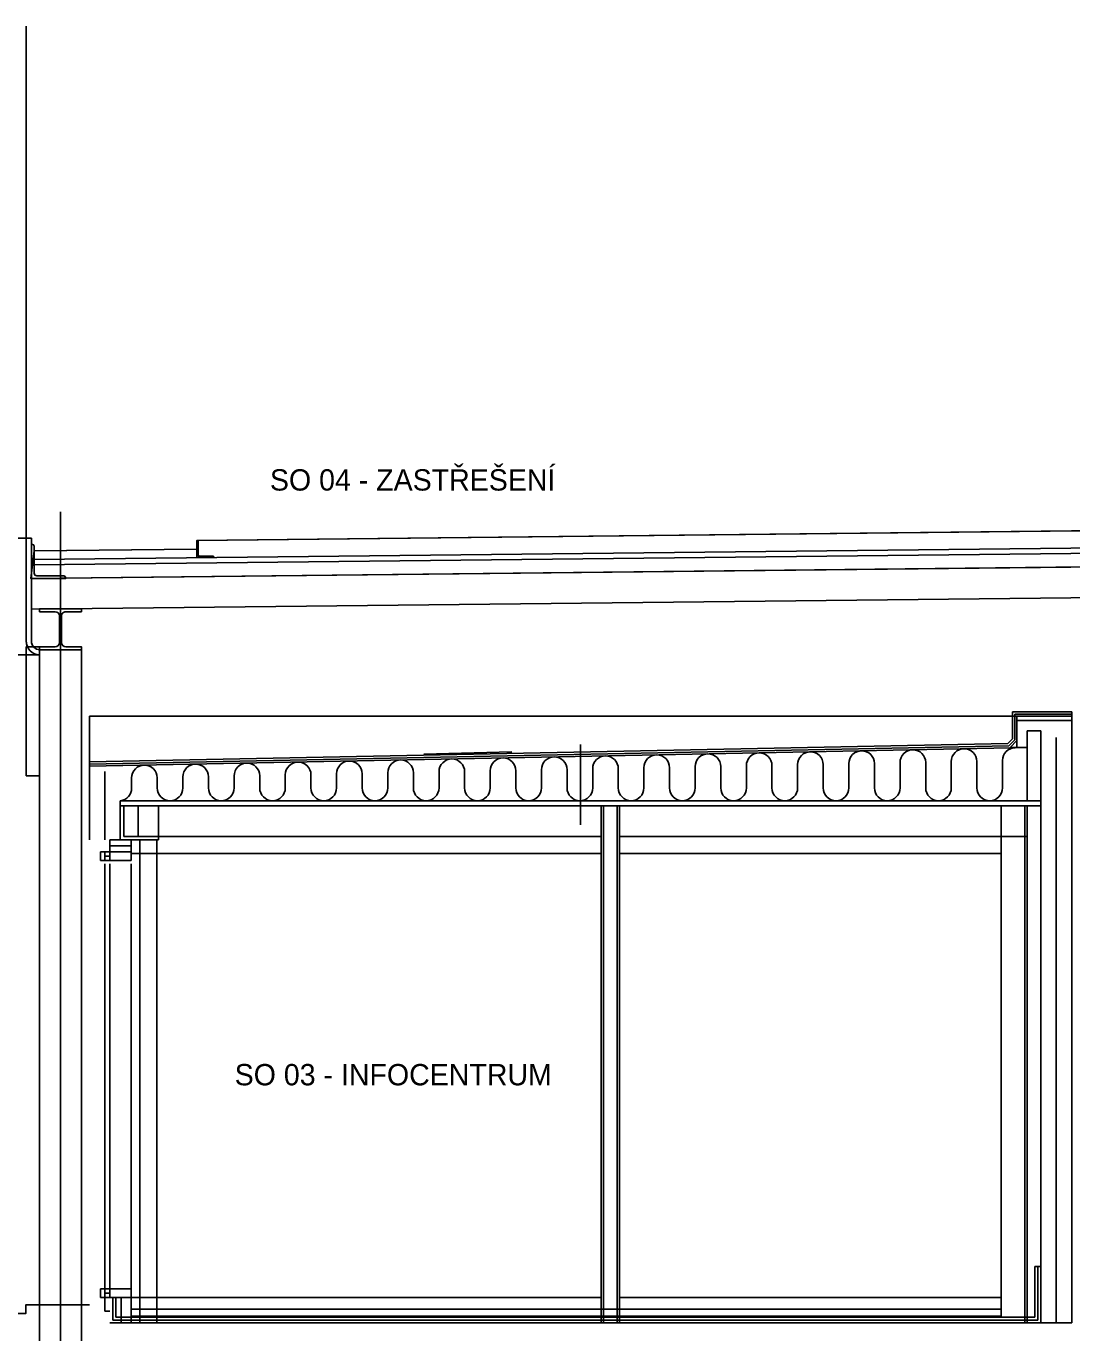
# Model space of a CAD drawing. Extents: x -438410 to -437811, y -1133174 to -1132817.
# Drawn here: x -437993.1 to -437962.48, y -1133028.74 to -1132990.45 of the extents above; entities that cross this region are included whole.
import ezdxf

# ---------------------------------------------------------------- set-up
doc = ezdxf.new("R2010")
doc.units = 0
for name, color, linetype in [('0100-STENY_REZ', 7, 'Continuous'), ('Default', 7, 'Continuous'), ('OSY', 7, 'Continuous'), ('S_IZOLACE', 7, 'Continuous'), ('S_KOTY_DILCI', 7, 'Continuous'), ('S_RASTR', 7, 'Continuous'), ('S_SKLO', 7, 'Continuous'), ('S_STENY_PODROVINOU', 7, 'Continuous'), ('S_STENY_REZ', 7, 'Continuous'), ('SILNA 1', 7, 'Continuous'), ('SILNA 2', 7, 'Continuous'), ('TECKA', 7, 'Continuous'), ('TENKA', 7, 'Continuous')]:
    doc.layers.add(name, color=color, linetype=linetype)

# ---------------------------------------------------------------- blocks, each defined once
blk = doc.blocks.new('fasada_sloupek_125')
at = {"layer": 'Default'}
for p, q in [((-0.25, 1.55), (-0.25, 1.25)), ((0, 1.55), (0, 1.25)), ((0.25, 1.55), (0.25, 1.25))]:
    blk.add_line(p, q, dxfattribs=at)
for points in [[(0.25, 1.55), (-0.25, 1.55), (-0.25, 1.8), (0.25, 1.8)], [(0.25, 0), (-0.25, 0), (-0.25, 1.25), (0.25, 1.25)]]:
    blk.add_lwpolyline(points, close=True, dxfattribs=at)
blk = doc.blocks.new('A$C21FA5ADA')
at = {"layer": 'Default'}
for p, q in [((317922, 164226), (317892, 164226)), ((317892, 164226), (317892, 163226)), ((317972, 164176), (317972, 163386)), ((317892, 163226), (318892, 163226)), ((318052, 163306), (318842, 163306)), ((318892, 163226), (318892, 163256))]:
    blk.add_line(p, q, dxfattribs=at)
for points in [[(317922, 164226), (317892, 164226), (317892, 163226), (318892, 163226), (318892, 163256)], [(317972, 163386), (317972, 164176)], [(318842, 163306), (318052, 163306)]]:
    blk.add_lwpolyline(points, dxfattribs=at)
for centre, radius, start, end in [((317922, 164176), 50, 0, 90), ((317922, 164176), 50, 0, 90), ((318052, 163386), 80, 180, 270), ((318052, 163386), 80, 180, 270), ((318842, 163256), 50, 0, 90), ((318842, 163256), 50, 0, 90)]:
    blk.add_arc(centre, radius, start, end, dxfattribs=at)

msp = doc.modelspace()

# ---------------------------------------------------------------- linework, layer by layer
at = {"layer": 'Default'}
for p, q in [((-437946.184, -1133005.562), (-437992.874, -1133006.076)), ((-437946.184, -1133005.722), (-437992.874, -1133006.236)), ((-437946.179, -1133006.122), (-437992.954, -1133006.637)), ((-437946.478, -1133007.026), (-437992.954, -1133007.537)), ((-437992.709, -1133008.722), (-437992.709, -1133031.164)), ((-437991.484, -1133008.715), (-437991.484, -1133031.164))]:
    msp.add_line(p, q, dxfattribs=at)
for points in [[(-437992.947, -1133005.457), (-437993.097, -1133005.457), (-437993.097, -1133008.472)], [(-437992.947, -1133008.472), (-437992.947, -1133005.457)], [(-437993.062, -1133008.635), (-437992.887, -1133008.635)]]:
    msp.add_lwpolyline(points, dxfattribs=at)
for radius, end in [(0.4, 204.111), (0.25, 220.8143)]:
    msp.add_arc((-437992.697, -1133008.472), radius, 180.0001, end, dxfattribs=at)
at = {"layer": 'DEFPOINTS'}
msp.add_lwpolyline([(-437992.867, -1133005.822), (-437992.96, -1133006.637), (-437946.179, -1133006.122), (-437946.184, -1133005.561), (-437946.259, -1133005.358), (-437950.606, -1133005.358), (-437950.633, -1133005.111), (-437988.098, -1133005.523), (-437988.106, -1133005.773), (-437992.867, -1133005.822)], dxfattribs=at)
at = {"layer": 'OSY'}
msp.add_line((-437992.096, -1133004.681), (-437992.096, -1133031.164), dxfattribs=at)
at = {"layer": 'S_IZOLACE'}
for p, q in [((-437964.156, -1133011.359), (-437964.156, -1133010.609)), ((-437964.156, -1133010.609), (-437962.488, -1133010.609)), ((-437962.938, -1133028.446), (-437962.938, -1133011.296)), ((-437991.245, -1133012.071), (-437964.33, -1133011.533)), ((-437964.33, -1133011.533), (-437964.156, -1133011.359)), ((-437969.013, -1133012.771), (-437969.013, -1133012.057)), ((-437968.263, -1133012.771), (-437968.263, -1133012.057)), ((-437967.513, -1133012.771), (-437967.513, -1133012.027)), ((-437966.763, -1133012.771), (-437966.763, -1133012.027)), ((-437966.013, -1133012.771), (-437966.013, -1133011.997)), ((-437965.263, -1133012.771), (-437965.263, -1133011.997)), ((-437964.513, -1133012.771), (-437964.513, -1133011.967)), ((-437990.794, -1133012.293), (-437990.794, -1133014.296)), ((-437988.513, -1133012.771), (-437988.513, -1133012.447)), ((-437987.763, -1133012.771), (-437987.763, -1133012.447)), ((-437987.013, -1133012.771), (-437987.013, -1133012.417)), ((-437986.263, -1133012.771), (-437986.263, -1133012.417)), ((-437985.513, -1133012.771), (-437985.513, -1133012.387)), ((-437984.763, -1133012.771), (-437984.763, -1133012.387)), ((-437984.013, -1133012.771), (-437984.013, -1133012.357)), ((-437983.263, -1133012.771), (-437983.263, -1133012.357)), ((-437982.513, -1133012.771), (-437982.513, -1133012.327)), ((-437981.763, -1133012.771), (-437981.763, -1133012.327)), ((-437981.013, -1133012.771), (-437981.013, -1133012.297)), ((-437980.263, -1133012.771), (-437980.263, -1133012.297)), ((-437979.513, -1133012.771), (-437979.513, -1133012.267)), ((-437978.763, -1133012.771), (-437978.763, -1133012.267)), ((-437978.013, -1133012.771), (-437978.013, -1133012.237)), ((-437977.263, -1133012.771), (-437977.263, -1133012.237)), ((-437976.513, -1133012.771), (-437976.513, -1133012.207)), ((-437975.763, -1133012.771), (-437975.763, -1133012.207)), ((-437975.013, -1133012.771), (-437975.013, -1133012.177)), ((-437974.263, -1133012.771), (-437974.263, -1133012.177)), ((-437973.513, -1133012.771), (-437973.513, -1133012.147)), ((-437972.763, -1133012.771), (-437972.763, -1133012.147)), ((-437972.013, -1133012.771), (-437972.013, -1133012.117)), ((-437971.263, -1133012.771), (-437971.263, -1133012.117)), ((-437970.513, -1133012.771), (-437970.513, -1133012.087)), ((-437969.763, -1133012.771), (-437969.763, -1133012.087)), ((-437990.013, -1133012.774), (-437990.013, -1133012.477)), ((-437989.263, -1133012.771), (-437989.263, -1133012.477)), ((-437990.023, -1133014.471), (-437990.648, -1133014.471)), ((-437963.476, -1133028.359), (-437963.476, -1133026.795)), ((-437990.561, -1133027.696), (-437990.561, -1133028.359)), ((-437990.323, -1133027.696), (-437990.323, -1133028.446)), ((-437990.561, -1133028.359), (-437963.476, -1133028.359)), ((-437964.554, -1133028.246), (-437990.023, -1133028.246))]:
    msp.add_line(p, q, dxfattribs=at)
for centre, start, end in [((-437968.638, -1133012.057), 89.9999, 179.9999), ((-437968.638, -1133012.057), 359.9999, 89.9999), ((-437967.138, -1133012.027), 89.9999, 179.9999), ((-437967.138, -1133012.027), 359.9999, 89.9999), ((-437965.638, -1133011.997), 89.9999, 179.9999), ((-437965.638, -1133011.997), 359.9999, 89.9999), ((-437964.138, -1133011.967), 89.9999, 179.9999), ((-437988.138, -1133012.447), 89.9999, 179.9999), ((-437988.138, -1133012.447), 359.9999, 89.9999), ((-437986.638, -1133012.417), 89.9999, 179.9999), ((-437986.638, -1133012.417), 359.9999, 89.9999), ((-437985.138, -1133012.387), 89.9999, 179.9999), ((-437985.138, -1133012.387), 359.9999, 89.9999), ((-437983.638, -1133012.357), 89.9999, 179.9999), ((-437983.638, -1133012.357), 359.9999, 89.9999), ((-437982.138, -1133012.327), 89.9999, 179.9999), ((-437982.138, -1133012.327), 359.9999, 89.9999), ((-437980.638, -1133012.297), 89.9999, 179.9999), ((-437980.638, -1133012.297), 359.9999, 89.9999), ((-437979.138, -1133012.267), 89.9999, 179.9999), ((-437979.138, -1133012.267), 359.9999, 89.9999), ((-437977.638, -1133012.237), 89.9999, 179.9999), ((-437977.638, -1133012.237), 359.9999, 89.9999), ((-437976.138, -1133012.207), 89.9999, 179.9999), ((-437976.138, -1133012.207), 359.9999, 89.9999), ((-437974.638, -1133012.177), 89.9999, 179.9999), ((-437974.638, -1133012.177), 359.9999, 89.9999), ((-437973.138, -1133012.147), 89.9999, 179.9999), ((-437973.138, -1133012.147), 359.9999, 89.9999), ((-437971.638, -1133012.117), 89.9999, 179.9999), ((-437971.638, -1133012.117), 359.9999, 89.9999), ((-437970.138, -1133012.087), 89.9999, 179.9999), ((-437970.138, -1133012.087), 359.9999, 89.9999), ((-437989.638, -1133012.477), 89.9999, 179.9999), ((-437989.638, -1133012.477), 359.9999, 89.9999), ((-437990.388, -1133012.774), 276.7795, 359.9999), ((-437988.888, -1133012.771), 179.9999, 269.9999), ((-437988.888, -1133012.771), 269.9999, 359.9999), ((-437987.388, -1133012.771), 179.9999, 269.9999), ((-437987.388, -1133012.771), 269.9999, 359.9999), ((-437985.888, -1133012.771), 179.9999, 269.9999), ((-437985.888, -1133012.771), 269.9999, 359.9999), ((-437984.388, -1133012.771), 179.9999, 269.9999), ((-437984.388, -1133012.771), 269.9999, 359.9999), ((-437982.888, -1133012.771), 179.9999, 269.9999), ((-437982.888, -1133012.771), 269.9999, 359.9999), ((-437981.388, -1133012.771), 179.9999, 269.9999), ((-437981.388, -1133012.771), 269.9999, 359.9999), ((-437979.888, -1133012.771), 179.9999, 269.9999), ((-437979.888, -1133012.771), 269.9999, 359.9999), ((-437978.388, -1133012.771), 179.9999, 269.9999), ((-437978.388, -1133012.771), 269.9999, 359.9999), ((-437976.888, -1133012.771), 179.9999, 269.9999), ((-437976.888, -1133012.771), 269.9999, 359.9999), ((-437975.388, -1133012.771), 179.9999, 269.9999), ((-437975.388, -1133012.771), 269.9999, 359.9999), ((-437973.888, -1133012.771), 179.9999, 269.9999), ((-437973.888, -1133012.771), 269.9999, 359.9999), ((-437972.388, -1133012.771), 179.9999, 269.9999), ((-437972.388, -1133012.771), 269.9999, 359.9999), ((-437970.888, -1133012.771), 179.9999, 269.9999), ((-437970.888, -1133012.771), 269.9999, 359.9999), ((-437969.388, -1133012.771), 179.9999, 269.9999), ((-437969.388, -1133012.771), 269.9999, 359.9999), ((-437967.888, -1133012.771), 179.9999, 269.9999), ((-437967.888, -1133012.771), 269.9999, 359.9999), ((-437966.388, -1133012.771), 179.9999, 269.9999), ((-437966.388, -1133012.771), 269.9999, 359.9999), ((-437964.888, -1133012.771), 179.9999, 269.9999), ((-437964.888, -1133012.771), 269.9999, 359.9999)]:
    msp.add_arc(centre, 0.375, start, end, dxfattribs=at)
at = {"layer": 'S_KOTY_DILCI'}
msp.add_line((-437981.454, -1133011.777), (-437978.881, -1133011.718), dxfattribs=at)
at = {"layer": 'S_RASTR'}
msp.add_line((-437976.866, -1133013.854), (-437976.866, -1133011.494), dxfattribs=at)
at = {"layer": 'S_SKLO'}
for p, q in [((-437990.798, -1133027.546), (-437990.798, -1133014.996)), ((-437990.648, -1133027.546), (-437990.648, -1133014.996)), ((-437990.798, -1133027.696), (-437990.798, -1133028.096)), ((-437990.798, -1133028.096), (-437990.648, -1133028.096))]:
    msp.add_line(p, q, dxfattribs=at)
at = {"layer": 'S_STENY_PODROVINOU'}
for p, q in [((-437964.218, -1133011.333), (-437964.218, -1133010.546)), ((-437964.218, -1133010.546), (-437962.488, -1133010.546)), ((-437962.488, -1133010.546), (-437962.488, -1133010.671)), ((-437964.093, -1133010.671), (-437991.244, -1133010.671)), ((-437991.244, -1133010.671), (-437991.244, -1133012.134)), ((-437964.093, -1133010.796), (-437962.488, -1133010.796)), ((-437963.793, -1133013.146), (-437963.793, -1133011.096)), ((-437963.388, -1133011.096), (-437963.793, -1133011.096)), ((-437963.388, -1133013.146), (-437963.388, -1133011.096)), ((-437991.247, -1133012.009), (-437964.356, -1133011.471)), ((-437963.793, -1133011.585), (-437991.244, -1133012.134)), ((-437964.356, -1133011.471), (-437964.218, -1133011.333)), ((-437964.293, -1133011.585), (-437964.093, -1133011.385)), ((-437964.093, -1133011.585), (-437964.293, -1133011.585)), ((-437964.093, -1133011.385), (-437964.093, -1133011.585)), ((-437964.093, -1133011.585), (-437963.793, -1133011.585)), ((-437991.247, -1133012.009), (-437991.244, -1133012.134)), ((-437963.388, -1133013.296), (-437963.388, -1133013.146)), ((-437976.261, -1133013.296), (-437975.731, -1133013.296)), ((-437976.198, -1133028.446), (-437976.198, -1133013.296)), ((-437975.793, -1133028.446), (-437975.793, -1133013.296)), ((-437963.793, -1133027.796), (-437963.793, -1133013.296)), ((-437963.388, -1133027.796), (-437963.388, -1133013.296)), ((-437990.648, -1133014.646), (-437990.648, -1133014.296)), ((-437990.023, -1133014.296), (-437990.648, -1133014.296)), ((-437989.824, -1133014.196), (-437990.244, -1133014.196)), ((-437990.023, -1133014.646), (-437990.023, -1133014.296)), ((-437989.273, -1133014.196), (-437989.773, -1133014.196)), ((-437989.773, -1133014.296), (-437989.773, -1133027.796)), ((-437989.273, -1133014.296), (-437989.273, -1133027.796)), ((-437976.261, -1133014.196), (-437989.224, -1133014.196)), ((-437963.793, -1133014.196), (-437975.731, -1133014.196)), ((-437990.023, -1133014.996), (-437990.023, -1133027.446)), ((-437963.563, -1133028.271), (-437963.563, -1133026.795)), ((-437963.563, -1133026.795), (-437963.388, -1133026.795)), ((-437990.473, -1133027.696), (-437990.648, -1133027.696)), ((-437990.473, -1133027.696), (-437990.473, -1133028.271)), ((-437990.023, -1133027.696), (-437990.023, -1133028.446)), ((-437989.773, -1133027.696), (-437989.773, -1133028.446)), ((-437989.273, -1133027.696), (-437989.273, -1133028.446)), ((-437976.261, -1133027.696), (-437976.261, -1133028.446)), ((-437975.731, -1133027.696), (-437975.731, -1133028.446)), ((-437964.554, -1133027.696), (-437964.554, -1133028.271)), ((-437963.856, -1133027.696), (-437963.856, -1133028.446)), ((-437963.793, -1133027.696), (-437963.793, -1133028.446)), ((-437963.388, -1133027.696), (-437963.388, -1133028.446)), ((-437964.554, -1133028.046), (-437990.023, -1133028.046)), ((-437962.488, -1133027.796), (-437962.488, -1133028.446)), ((-437962.888, -1133028.446), (-437990.648, -1133028.446)), ((-437990.473, -1133028.271), (-437963.563, -1133028.271)), ((-437962.888, -1133028.446), (-437962.588, -1133028.446)), ((-437962.488, -1133028.446), (-437962.588, -1133028.446))]:
    msp.add_line(p, q, dxfattribs=at)
at = {"layer": 'S_STENY_REZ'}
for p, q in [((-437964.093, -1133011.585), (-437964.093, -1133010.671)), ((-437964.093, -1133010.671), (-437962.488, -1133010.671)), ((-437962.488, -1133027.796), (-437962.488, -1133010.671)), ((-437991.244, -1133012.134), (-437991.244, -1133014.293)), ((-437990.344, -1133013.146), (-437990.344, -1133014.296)), ((-437963.388, -1133013.146), (-437990.344, -1133013.146)), ((-437976.261, -1133013.296), (-437990.344, -1133013.296)), ((-437990.244, -1133013.296), (-437990.244, -1133014.196)), ((-437976.261, -1133027.696), (-437976.261, -1133013.296)), ((-437963.388, -1133013.296), (-437975.731, -1133013.296)), ((-437975.731, -1133027.696), (-437975.731, -1133013.296)), ((-437964.554, -1133027.696), (-437964.554, -1133013.296)), ((-437963.856, -1133027.796), (-437963.856, -1133013.296)), ((-437989.223, -1133014.296), (-437990.344, -1133014.296)), ((-437990.244, -1133014.196), (-437989.824, -1133014.196)), ((-437989.223, -1133014.296), (-437989.223, -1133014.196)), ((-437976.261, -1133014.696), (-437990.023, -1133014.696)), ((-437964.554, -1133014.696), (-437975.731, -1133014.696)), ((-437976.261, -1133027.696), (-437990.023, -1133027.696)), ((-437964.554, -1133027.696), (-437975.731, -1133027.696))]:
    msp.add_line(p, q, dxfattribs=at)
msp.add_lwpolyline([(-437989.823, -1133014.196), (-437989.223, -1133014.196), (-437989.223, -1133013.296), (-437989.823, -1133013.296)], close=True, dxfattribs=at)
at = {"layer": 'SILNA 1'}
for p, q in [((-437950.633, -1133005.111), (-437988.106, -1133005.523)), ((-437993.097, -1133005.457), (-437993.097, -1133008.472)), ((-437993.097, -1133005.457), (-437992.947, -1133005.457)), ((-437992.947, -1133005.457), (-437992.947, -1133008.472)), ((-437988.106, -1133005.773), (-437992.876, -1133005.822)), ((-437992.867, -1133006.477), (-437992.867, -1133005.687)), ((-437991.947, -1133006.626), (-437992.096, -1133006.627)), ((-437992.096, -1133006.627), (-437991.947, -1133006.626)), ((-437991.947, -1133006.626), (-437991.947, -1133006.607)), ((-437992.709, -1133007.609), (-437992.709, -1133007.522)), ((-437992.709, -1133007.522), (-437991.484, -1133007.522)), ((-437992.251, -1133007.609), (-437992.709, -1133007.609)), ((-437992.127, -1133008.512), (-437992.127, -1133007.732)), ((-437992.096, -1133008.722), (-437992.096, -1133007.522)), ((-437992.065, -1133007.732), (-437992.065, -1133008.512)), ((-437991.484, -1133007.609), (-437991.942, -1133007.609)), ((-437991.484, -1133007.522), (-437991.484, -1133007.609)), ((-437992.709, -1133008.722), (-437992.709, -1133008.635)), ((-437992.709, -1133008.635), (-437992.251, -1133008.635)), ((-437991.942, -1133008.635), (-437991.484, -1133008.635)), ((-437991.484, -1133008.635), (-437991.484, -1133008.722)), ((-437991.484, -1133008.722), (-437992.709, -1133008.722))]:
    msp.add_line(p, q, dxfattribs=at)
for points in [[(-437988.091, -1133005.523), (-437988.092, -1133005.523), (-437988.106, -1133005.523), (-437988.106, -1133006.023), (-437987.606, -1133006.018), (-437987.606, -1133006.008)], [(-437988.066, -1133005.943), (-437988.066, -1133005.548)], [(-437992.917, -1133005.637), (-437992.947, -1133005.637), (-437992.947, -1133006.637), (-437992.096, -1133006.627), (-437992.096, -1133006.557), (-437992.787, -1133006.557)], [(-437987.631, -1133005.983), (-437988.026, -1133005.983)], [(-437992.096, -1133006.627), (-437992.947, -1133006.637), (-437992.947, -1133006.637), (-437992.096, -1133006.637), (-437992.096, -1133006.627)], [(-437991.997, -1133006.557), (-437992.096, -1133006.557), (-437992.096, -1133006.627)], [(-437992.096, -1133006.627), (-437992.096, -1133006.637), (-437991.947, -1133006.637), (-437991.947, -1133006.626)], [(-437992.251, -1133007.609), (-437992.709, -1133007.609), (-437992.709, -1133007.522), (-437991.484, -1133007.522), (-437991.484, -1133007.609), (-437991.942, -1133007.609)], [(-437992.127, -1133008.512), (-437992.127, -1133007.732)], [(-437992.065, -1133007.732), (-437992.065, -1133008.512)], [(-437991.942, -1133008.635), (-437991.484, -1133008.635), (-437991.484, -1133008.722), (-437992.709, -1133008.722), (-437992.709, -1133008.635), (-437992.251, -1133008.635)]]:
    msp.add_lwpolyline(points, dxfattribs=at)
msp.add_lwpolyline([(-437993.097, -1133012.414), (-437992.709, -1133012.414), (-437992.709, -1133008.635), (-437993.097, -1133008.635)], close=True, dxfattribs=at)
for centre, radius, start, end in [((-437988.091, -1133005.548), 0.025, 0.0001, 90.6303), ((-437992.917, -1133005.687), 0.05, 0.0001, 90.0001), ((-437988.026, -1133005.943), 0.04, 180.0098, 270.0001), ((-437987.631, -1133006.008), 0.025, 0.0001, 90.0001), ((-437992.787, -1133006.477), 0.08, 180.0001, 270.007), ((-437991.997, -1133006.607), 0.05, 0.0001, 90.0001), ((-437992.251, -1133007.732), 0.124, 0.0001, 90.0001), ((-437992.251, -1133007.732), 0.124, 0.0001, 90.0001), ((-437991.942, -1133007.732), 0.124, 90.0001, 180.0001), ((-437991.942, -1133007.732), 0.124, 90.0001, 180.0001), ((-437992.697, -1133008.472), 0.4, 180.0001, 270.0001), ((-437992.697, -1133008.472), 0.25, 180.0001, 270.0001), ((-437992.251, -1133008.512), 0.124, 270.0001, 0.0001), ((-437992.251, -1133008.512), 0.124, 270.0001, 0.0001), ((-437991.942, -1133008.512), 0.124, 180.0001, 270.0001), ((-437991.942, -1133008.512), 0.124, 180.0001, 270.0001)]:
    msp.add_arc(centre, radius, start, end, dxfattribs=at)
at = {"layer": 'SILNA 2'}
msp.add_lwpolyline([(-437991.25, -1133027.914), (-437993.106, -1133027.914), (-437993.106, -1133028.166), (-438036.864, -1133028.166)], dxfattribs=at)
at = {"layer": 'TECKA'}
msp.add_line((-437993.097, -1132990.452), (-437993.097, -1133006.132), dxfattribs=at)
at = {"layer": 'TENKA'}
for p, q in [((-438036.864, -1133005.457), (-437993.097, -1133005.457)), ((-438036.864, -1133008.872), (-437992.709, -1133008.872))]:
    msp.add_line(p, q, dxfattribs=at)

# ---------------------------------------------------------------- block references
at = {"layer": '0100-STENY_REZ', "xscale": 0.49999999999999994, "yscale": -0.49999999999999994, "rotation": -90.00000003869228}
for p in [(-437990.023, -1133014.771), (-437990.023, -1133027.571)]:
    msp.add_blockref('fasada_sloupek_125', p, dxfattribs=at)
at = {"layer": 'SILNA 1', "rotation": 6.099379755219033e-05}
for p, xscale, yscale in [((-438147.052, -1133087.637), 0.0004999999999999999, 0.0004999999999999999), ((-438310.84, -1133169.864), 0.0009999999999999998, 0.0009999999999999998)]:
    msp.add_blockref('A$C21FA5ADA', p, dxfattribs=dict(at, xscale=xscale, yscale=yscale))

# ---------------------------------------------------------------- texts
at = {"layer": 'Default'}
for s, p in [('SO 04 - ZASTŘEŠENÍ', (-437985.964, -1133004.059)), ('SO 03 - INFOCENTRUM', (-437986.996, -1133021.484))]:
    msp.add_text(s, height=0.625, rotation=360, dxfattribs=at).set_placement(p)

doc.saveas('drawing.dxf')
